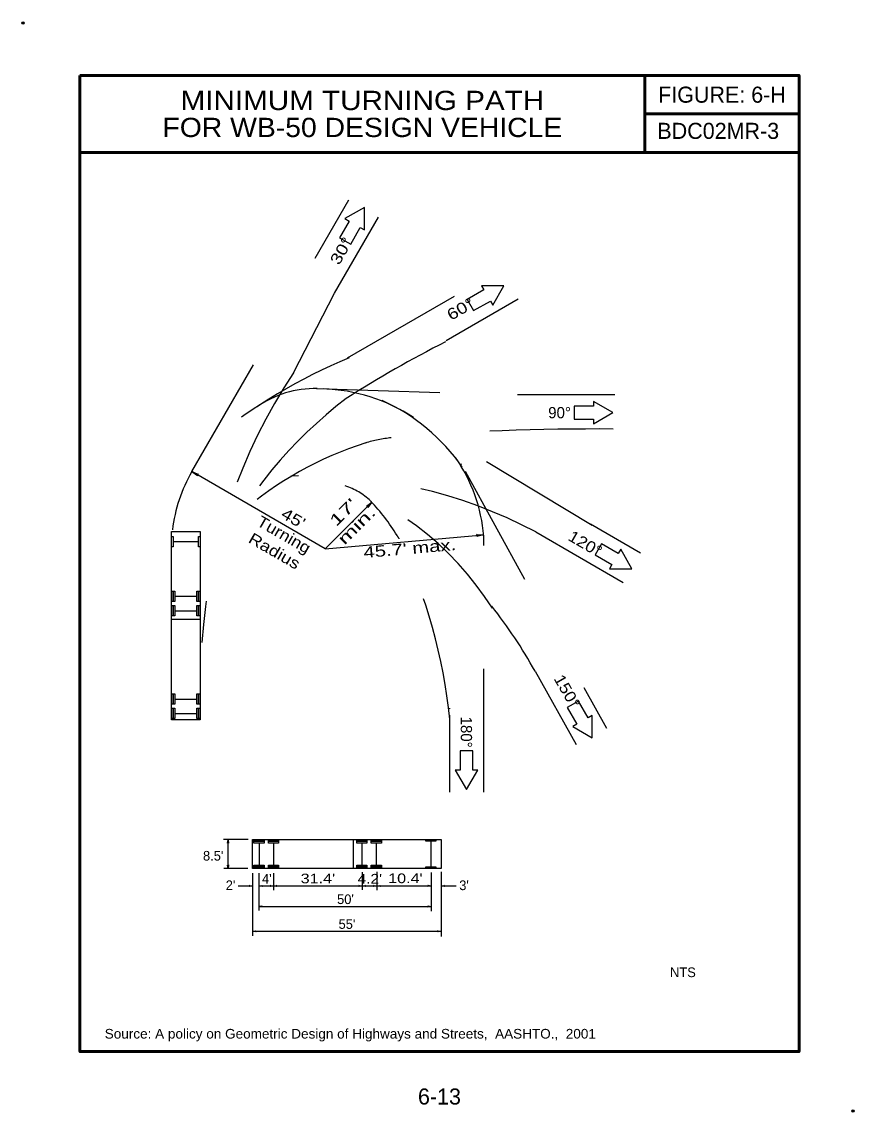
# Model space of a CAD drawing. Extents: x -4.775 to -4.1, y 4.883 to 5.768.
import ezdxf
from ezdxf.enums import TextEntityAlignment as Align

# ---------------------------------------------------------------- set-up
doc = ezdxf.new("R2010")
doc.units = 0
doc.header["$LTSCALE"] = 0.0036
doc.header["$PDMODE"] = 32
doc.header["$PDSIZE"] = 0.0018
doc.linetypes.add('LONG_DASHED', pattern=[7.5, 6, -1.5])
doc.layers.add('1', color=7, linetype='Continuous', lineweight=25)
doc.layers.add('2', color=7, linetype='Continuous', lineweight=25)

msp = doc.modelspace()

# ---------------------------------------------------------------- linework, layer by layer
at = {"layer": '1', "lineweight": 53}
for p, q in [((-4.269458, 5.724317), (-4.269458, 5.661817)), ((-4.269458, 5.693067), (-4.144458, 5.693067)), ((-4.727792, 5.661817), (-4.144458, 5.661817))]:
    msp.add_line(p, q, dxfattribs=at)
at = {"layer": '1', "linetype": 'LONG_DASHED'}
for p, q in [((-4.636958, 5.40295), (-4.509708, 5.623342)), ((-4.521283, 5.547725), (-4.485642, 5.609442)), ((-4.510592, 5.495242), (-4.386167, 5.567075)), ((-4.554392, 5.483133), (-4.521283, 5.547725)), ((-4.430658, 5.509308), (-4.372267, 5.543017)), ((-4.535717, 5.4704), (-4.373417, 5.465158)), ((-4.372767, 5.46545), (-4.293908, 5.46545)), ((-4.312242, 5.359308), (-4.45725, 5.446858)), ((-4.418583, 5.409233), (-4.418383, 5.408883)), ((-4.415308, 5.403283), (-4.300725, 5.194808)), ((-4.313583, 5.360575), (-4.273167, 5.337242)), ((-4.357925, 5.3541), (-4.28705, 5.313183)), ((-4.358617, 5.241142), (-4.325158, 5.181558))]:
    msp.add_line(p, q, dxfattribs=at)
at = {"layer": '1'}
for p, q in [((-4.636842, 5.402892), (-4.631792, 5.400933)), ((-4.490967, 5.378158), (-4.494175, 5.3738)), ((-4.4005, 5.35165), (-4.405758, 5.350392)), ((-4.652158, 5.346175), (-4.631508, 5.346175)), ((-4.650758, 5.3019), (-4.632908, 5.3019)), ((-4.650758, 5.290183), (-4.632908, 5.290183)), ((-4.65355, 5.2833), (-4.630117, 5.2833)), ((-4.650758, 5.218567), (-4.632908, 5.218567)), ((-4.650758, 5.20685), (-4.632908, 5.20685)), ((-4.591308, 5.10455), (-4.611283, 5.10455)), ((-4.60755, 5.081017), (-4.60755, 5.10435)), ((-4.607533, 5.104467), (-4.607133, 5.101783)), ((-4.505975, 5.10455), (-4.505975, 5.081108)), ((-4.4431, 5.10315), (-4.4431, 5.082508)), ((-4.582425, 5.101758), (-4.582425, 5.0839)), ((-4.570708, 5.101758), (-4.570708, 5.0839)), ((-4.499092, 5.101758), (-4.499092, 5.0839)), ((-4.487375, 5.101758), (-4.487375, 5.0839)), ((-4.591425, 5.081108), (-4.610933, 5.081108)), ((-4.607558, 5.081242), (-4.607958, 5.083925)), ((-4.587633, 5.077317), (-4.587633, 5.02655)), ((-4.582575, 5.077317), (-4.582575, 5.047025)), ((-4.5707, 5.077317), (-4.5707, 5.063425)), ((-4.498767, 5.0781), (-4.498767, 5.063758)), ((-4.486783, 5.078325), (-4.486783, 5.063642)), ((-4.442867, 5.077992), (-4.442867, 5.046383)), ((-4.43485, 5.078325), (-4.43485, 5.025983)), ((-4.582517, 5.067008), (-4.579842, 5.0674)), ((-4.570667, 5.066992), (-4.567992, 5.067392)), ((-4.498767, 5.067008), (-4.496092, 5.0674)), ((-4.486792, 5.067025), (-4.484117, 5.067425)), ((-4.434675, 5.067008), (-4.432, 5.067408)), ((-4.599375, 5.067008), (-4.587633, 5.067008)), ((-4.587667, 5.067008), (-4.590342, 5.066608)), ((-4.582575, 5.067008), (-4.442867, 5.067008)), ((-4.570717, 5.066983), (-4.573392, 5.066592)), ((-4.498842, 5.067008), (-4.501517, 5.066608)), ((-4.486883, 5.067008), (-4.489558, 5.066608)), ((-4.442908, 5.067033), (-4.445583, 5.066642)), ((-4.434708, 5.067008), (-4.422433, 5.067008)), ((-4.582467, 5.050433), (-4.579792, 5.050825)), ((-4.582458, 5.050425), (-4.442767, 5.050425)), ((-4.442842, 5.050392), (-4.445517, 5.049992)), ((-4.587617, 5.030242), (-4.43495, 5.030242)), ((-4.5876, 5.030258), (-4.584925, 5.03065)), ((-4.434875, 5.030242), (-4.43755, 5.02985))]:
    msp.add_line(p, q, dxfattribs=at)
at = {"layer": '1', "lineweight": 53}
msp.add_lwpolyline([(-4.727792, 5.724317), (-4.144458, 5.724317), (-4.144458, 4.93265), (-4.727792, 4.93265)], close=True, dxfattribs=at)
at = {"layer": '1'}
for points in [[(-4.517158, 5.592658), (-4.508133, 5.58745), (-4.500325, 5.600983), (-4.49695, 5.599025), (-4.496933, 5.617267), (-4.512742, 5.60815), (-4.509342, 5.606192)], [(-4.413592, 5.54255), (-4.408383, 5.533525), (-4.39485, 5.541342), (-4.392908, 5.53795), (-4.383783, 5.553742), (-4.402017, 5.553742), (-4.400058, 5.550358)], [(-4.326883, 5.456017), (-4.326883, 5.4456), (-4.311258, 5.4456), (-4.311258, 5.441692), (-4.295467, 5.450808), (-4.311258, 5.459925), (-4.311258, 5.456017)], [(-4.65355, 5.201642), (-4.65355, 5.354425), (-4.630117, 5.354425), (-4.630117, 5.201642)], [(-4.65355, 5.342008), (-4.65355, 5.350342), (-4.652158, 5.350342), (-4.652158, 5.342008)], [(-4.631508, 5.342008), (-4.631508, 5.350342), (-4.630117, 5.350342), (-4.630117, 5.342008)], [(-4.304617, 5.344467), (-4.309825, 5.335442), (-4.296292, 5.327633), (-4.29825, 5.324258), (-4.280008, 5.324242), (-4.289125, 5.34005), (-4.291083, 5.33665)], [(-4.65355, 5.297733), (-4.65355, 5.306067), (-4.652158, 5.306067), (-4.652158, 5.297733)], [(-4.652158, 5.297733), (-4.652158, 5.306067), (-4.650758, 5.306067), (-4.650758, 5.297733)], [(-4.632908, 5.297733), (-4.632908, 5.306067), (-4.631508, 5.306067), (-4.631508, 5.297733)], [(-4.631508, 5.297733), (-4.631508, 5.306067), (-4.630117, 5.306067), (-4.630117, 5.297733)], [(-4.65355, 5.286017), (-4.65355, 5.29435), (-4.652158, 5.29435), (-4.652158, 5.286017)], [(-4.652158, 5.286017), (-4.652158, 5.29435), (-4.650758, 5.29435), (-4.650758, 5.286017)], [(-4.632908, 5.286017), (-4.632908, 5.29435), (-4.631508, 5.29435), (-4.631508, 5.286017)], [(-4.631508, 5.286017), (-4.631508, 5.29435), (-4.630117, 5.29435), (-4.630117, 5.286017)], [(-4.65355, 5.2144), (-4.65355, 5.222733), (-4.652158, 5.222733), (-4.652158, 5.2144)], [(-4.652158, 5.2144), (-4.652158, 5.222733), (-4.650758, 5.222733), (-4.650758, 5.2144)], [(-4.632908, 5.2144), (-4.632908, 5.222733), (-4.631508, 5.222733), (-4.631508, 5.2144)], [(-4.631508, 5.2144), (-4.631508, 5.222733), (-4.630117, 5.222733), (-4.630117, 5.2144)], [(-4.65355, 5.202683), (-4.65355, 5.211017), (-4.652158, 5.211017), (-4.652158, 5.202683)], [(-4.652158, 5.202683), (-4.652158, 5.211017), (-4.650758, 5.211017), (-4.650758, 5.202683)], [(-4.632908, 5.202683), (-4.632908, 5.211017), (-4.631508, 5.211017), (-4.631508, 5.202683)], [(-4.631508, 5.202683), (-4.631508, 5.211017), (-4.630117, 5.211017), (-4.630117, 5.202683)], [(-4.323383, 5.216842), (-4.332408, 5.211633), (-4.324592, 5.1981), (-4.327975, 5.19615), (-4.312183, 5.187025), (-4.312183, 5.205267), (-4.315575, 5.203308)], [(-4.409033, 5.176492), (-4.41945, 5.176492), (-4.41945, 5.160867), (-4.42335, 5.160867), (-4.414242, 5.145075), (-4.405125, 5.160867), (-4.409033, 5.160867)], [(-4.587633, 5.10455), (-4.43485, 5.10455), (-4.43485, 5.081108), (-4.587633, 5.081108)], [(-4.586592, 5.10455), (-4.578258, 5.10455), (-4.578258, 5.10315), (-4.586592, 5.10315)], [(-4.586592, 5.10315), (-4.578258, 5.10315), (-4.578258, 5.101758), (-4.586592, 5.101758)], [(-4.574875, 5.10455), (-4.566542, 5.10455), (-4.566542, 5.10315), (-4.574875, 5.10315)], [(-4.574875, 5.10315), (-4.566542, 5.10315), (-4.566542, 5.101758), (-4.574875, 5.101758)], [(-4.503258, 5.10455), (-4.494925, 5.10455), (-4.494925, 5.10315), (-4.503258, 5.10315)], [(-4.503258, 5.10315), (-4.494925, 5.10315), (-4.494925, 5.101758), (-4.503258, 5.101758)], [(-4.491542, 5.10455), (-4.483208, 5.10455), (-4.483208, 5.10315), (-4.491542, 5.10315)], [(-4.491542, 5.10315), (-4.483208, 5.10315), (-4.483208, 5.101758), (-4.491542, 5.101758)], [(-4.447267, 5.10455), (-4.438933, 5.10455), (-4.438933, 5.10315), (-4.447267, 5.10315)], [(-4.586592, 5.0839), (-4.578258, 5.0839), (-4.578258, 5.082508), (-4.586592, 5.082508)], [(-4.586592, 5.082508), (-4.578258, 5.082508), (-4.578258, 5.081108), (-4.586592, 5.081108)], [(-4.574875, 5.0839), (-4.566542, 5.0839), (-4.566542, 5.082508), (-4.574875, 5.082508)], [(-4.574875, 5.082508), (-4.566542, 5.082508), (-4.566542, 5.081108), (-4.574875, 5.081108)], [(-4.503258, 5.0839), (-4.494925, 5.0839), (-4.494925, 5.082508), (-4.503258, 5.082508)], [(-4.503258, 5.082508), (-4.494925, 5.082508), (-4.494925, 5.081108), (-4.503258, 5.081108)], [(-4.491542, 5.0839), (-4.483208, 5.0839), (-4.483208, 5.082508), (-4.491542, 5.082508)], [(-4.491542, 5.082508), (-4.483208, 5.082508), (-4.483208, 5.081108), (-4.491542, 5.081108)], [(-4.447267, 5.082508), (-4.438933, 5.082508), (-4.438933, 5.081108), (-4.447267, 5.081108)]]:
    msp.add_lwpolyline(points, close=True, dxfattribs=at)
for points in [[(-4.632967, 5.4007), (-4.632492, 5.399433), (-4.636883, 5.402925)], [(-4.631792, 5.400908), (-4.632958, 5.400717), (-4.632967, 5.4007)], [(-4.494092, 5.374992), (-4.495425, 5.374867), (-4.490917, 5.3782)], [(-4.4942, 5.373817), (-4.494075, 5.374992), (-4.494092, 5.374992)], [(-4.404925, 5.351242), (-4.406042, 5.352017), (-4.400433, 5.35165)], [(-4.405767, 5.350408), (-4.404925, 5.351225), (-4.404925, 5.351242)], [(-4.607517, 5.102233), (-4.607958, 5.101717), (-4.607517, 5.104492)], [(-4.607142, 5.101775), (-4.607508, 5.102233), (-4.607517, 5.102233)], [(-4.60795, 5.083933), (-4.607575, 5.083475), (-4.607558, 5.083475)], [(-4.607558, 5.083475), (-4.607133, 5.083992), (-4.607558, 5.081217)], [(-4.589892, 5.067008), (-4.590417, 5.067433), (-4.587633, 5.067008)], [(-4.579833, 5.067392), (-4.580292, 5.067017), (-4.580292, 5.067008)], [(-4.57295, 5.066983), (-4.573467, 5.067408), (-4.570683, 5.066983)], [(-4.567975, 5.067383), (-4.568433, 5.067008), (-4.568433, 5.066992)], [(-4.501075, 5.067008), (-4.501592, 5.067433), (-4.498808, 5.067008)], [(-4.496083, 5.067392), (-4.496542, 5.067017), (-4.496542, 5.067008)], [(-4.489117, 5.067008), (-4.489633, 5.067433), (-4.48685, 5.067008)], [(-4.4841, 5.067408), (-4.484558, 5.067033), (-4.484558, 5.067025)], [(-4.445133, 5.067033), (-4.445658, 5.067467), (-4.442875, 5.067033)], [(-4.431983, 5.067392), (-4.432442, 5.067017), (-4.432442, 5.067008)], [(-4.59035, 5.066617), (-4.589892, 5.066992), (-4.589892, 5.067008)], [(-4.580292, 5.067008), (-4.579767, 5.066575), (-4.58255, 5.067008)], [(-4.573408, 5.0666), (-4.57295, 5.066975), (-4.57295, 5.066983)], [(-4.568433, 5.066992), (-4.567917, 5.066567), (-4.5707, 5.066992)], [(-4.501533, 5.066617), (-4.501075, 5.066992), (-4.501075, 5.067008)], [(-4.496542, 5.067008), (-4.496017, 5.066575), (-4.4988, 5.067008)], [(-4.489575, 5.066617), (-4.489117, 5.066992), (-4.489117, 5.067008)], [(-4.484558, 5.067025), (-4.484042, 5.0666), (-4.486825, 5.067025)], [(-4.445592, 5.06665), (-4.445133, 5.067025), (-4.445133, 5.067033)], [(-4.432442, 5.067008), (-4.431925, 5.066583), (-4.434708, 5.067008)], [(-4.580242, 5.050433), (-4.579717, 5.050008), (-4.5825, 5.050433)], [(-4.579783, 5.050817), (-4.580242, 5.050442), (-4.580242, 5.050433)], [(-4.445075, 5.050392), (-4.445592, 5.050817), (-4.442808, 5.050392)], [(-4.445533, 5.050008), (-4.445075, 5.050383), (-4.445075, 5.050392)], [(-4.585375, 5.030258), (-4.58485, 5.029825), (-4.587633, 5.030258)], [(-4.584917, 5.030642), (-4.585375, 5.030267), (-4.585375, 5.030258)], [(-4.4371, 5.030242), (-4.437625, 5.030675), (-4.434842, 5.030242)], [(-4.437558, 5.029858), (-4.4371, 5.030233), (-4.4371, 5.030242)]]:
    msp.add_lwpolyline(points, dxfattribs=at)
at = {"layer": '1', "linetype": 'LONG_DASHED'}
for centre, radius, start, end in [((-4.000004, 4.659644), 0.951917, 116.93664, 122.5244), ((-4.326551, 5.061725), 0.470649, 112.86889, 128.7179), ((-4.180535, 5.233818), 0.449362, 146.30223, 176.09092), ((-4.536767, 5.387836), 0.082555, 89.06105, 124.87125), ((-4.535249, 5.328156), 0.142037, 56.69041, 88.02417), ((-4.282566, 5.163935), 0.37623, 127.5395, 153.04567), ((-4.547968, 5.316029), 0.158745, 34.80526, 65.64696), ((-4.466, 5.332085), 0.098763, 95.33016, 107.80249), ((-4.308826, 3.4685), 1.969062, 89.60308, 94.83999), ((-4.411915, 5.157192), 0.281828, 107.33286, 131.17419), ((-4.528706, 5.340452), 0.128908, 4.55417, 34.99999), ((-4.528705, 5.340446), 0.125002, 149.99728, 172.95647), ((-4.541712, 5.006226), 0.393437, 62.15177, 92.17506), ((-4.607131, 5.156725), 0.253254, 32.31647, 73.72888), ((-4.528706, 5.340452), 0.053387, 46.66372, 72.39137), ((-4.612415, 5.264824), 0.1661, 31.30531, 43.46578), ((-4.668478, 5.213848), 0.240923, 33.98455, 34.8421), ((-4.864873, 5.158405), 0.439321, 5.73099, 25.46954), ((-4.693436, 5.055869), 0.382664, 28.95741, 38.44304)]:
    msp.add_arc(centre, radius, start, end, dxfattribs=at)
at = {"layer": '1'}
for p in [(-4.773967, 5.766875), (-4.100633, 4.884375)]:
    msp.add_point(p, dxfattribs=at)
at = {"layer": '2'}
for q in [(-4.636958, 5.40295), (-4.490958, 5.3782), (-4.400292, 5.351692)]:
    msp.add_line((-4.528708, 5.34045), q, dxfattribs=at)
at = {"layer": '2', "linetype": 'LONG_DASHED'}
for p, q in [((-4.400158, 5.143017), (-4.400158, 5.3504)), ((-4.427575, 5.210658), (-4.427575, 5.211142)), ((-4.427575, 5.143017), (-4.427575, 5.205433))]:
    msp.add_line(p, q, dxfattribs=at)

# ---------------------------------------------------------------- texts
at = {"layer": '1'}
for s, height, p in [('FIGURE: 6-H', 0.01303, (-4.206958, 5.702175)), ('BDC02MR-3', 0.01303, (-4.209988, 5.672817)), ("8.5'", 0.007817, (-4.619638, 5.087533)), ("4'", 0.007817, (-4.576167, 5.068842)), ("2'", 0.007817, (-4.605583, 5.063633)), ("3'", 0.007817, (-4.416183, 5.063575)), ("50'", 0.007817, (-4.512342, 5.052275)), ("55'", 0.007817, (-4.511142, 5.03215)), ('NTS', 0.007817, (-4.238646, 4.993008)), ('6-13', 0.01303, (-4.436125, 4.889683))]:
    msp.add_text(s, height=height, dxfattribs=at).set_placement(p, align=Align.CENTER)
for s, height, width, p in [('MINIMUM TURNING PATH', 0.01562, 1.15, (-4.498625, 5.696192)), ('FOR WB-50 DESIGN VEHICLE', 0.01562, 1.1, (-4.498625, 5.674317)), ("31.4'", 0.007817, 1.25, (-4.534713, 5.069108)), ("4.2'", 0.007817, 1.2, (-4.492617, 5.0689)), ("10.4'", 0.007817, 1.25, (-4.463746, 5.069242))]:
    msp.add_text(s, height=height, dxfattribs=dict(at, width=width)).set_placement(p, align=Align.CENTER)
for s, rotation, width, p in [('30°', 60, 1.25, (-4.506071, 5.589729)), ('60°', 30, 1.25, (-4.406763, 5.536724)), ('120°', 330, 1.15, (-4.307554, 5.333381)), ('150°', 300, 1.15, (-4.329222, 5.210013))]:
    msp.add_text(s, height=0.009108, rotation=rotation, dxfattribs=dict(at, width=width)).set_placement(p, align=Align.RIGHT)
msp.add_text('90°', height=0.009108, dxfattribs=at).set_placement((-4.329492, 5.44625), align=Align.RIGHT)
for s, rotation, width, p in [("17'", 45, 1.6, (-4.51094, 5.366843)), ("45'", 329.999, 1.25, (-4.556842, 5.361238)), ('min.', 45, 1.6, (-4.500082, 5.355977)), ('Turning', 329.999, 1.15, (-4.564521, 5.347932)), ('Radius', 329.999, 1.2, (-4.572204, 5.334629)), ("45.7' max.", 5.002, 1.35, (-4.459806, 5.33616))]:
    msp.add_text(s, height=0.009117, rotation=rotation, dxfattribs=dict(at, width=width)).set_placement(p, align=Align.CENTER)
msp.add_text('180°', height=0.009108, rotation=270, dxfattribs=at).set_placement((-4.4188, 5.1791), align=Align.RIGHT)
at = {"layer": '1', "width": 1.05}
msp.add_text('Source: A policy on Geometric Design of Highways and Streets,  AASHTO.,  2001', height=0.007817, dxfattribs=at).set_placement((-4.707608, 4.943192))

doc.saveas('drawing.dxf')
